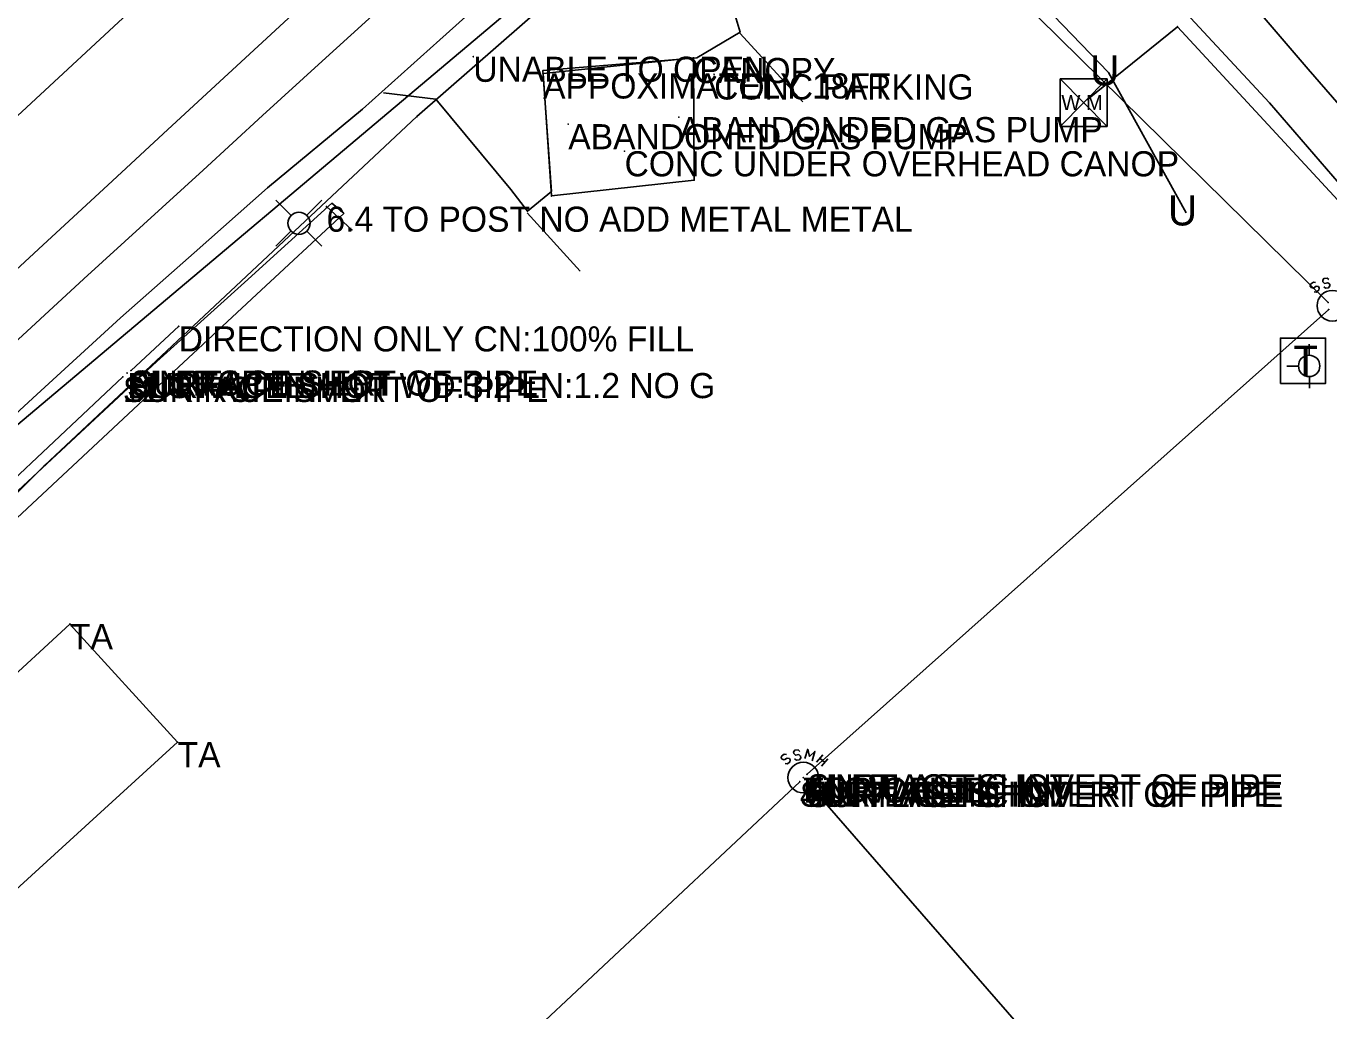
# Model space of a CAD drawing. Extents: x 1660112 to 1662239, y 668919 to 671377.
# Drawn here: x 1661444.9 to 1661704.2, y 669604.5 to 669800.5 of the extents above; entities that cross this region are included whole.
import ezdxf

# ---------------------------------------------------------------- set-up
doc = ezdxf.new("R2010")
doc.units = 0
for name, color, linetype in [('Default', 7, 'Continuous'), ('S_BASELINE', 7, 'Continuous'), ('S_BUILDING', 7, 'Continuous'), ('S_BUILDING_ANNOT', 7, 'Continuous'), ('S_DRG_PT_SYM', 7, 'Continuous'), ('S_DROP_INLET_ANNOT', 7, 'Continuous'), ('S_EDGE_CONCRETE', 7, 'Continuous'), ('S_EDGE_PAVEMENT', 7, 'Continuous'), ('S_FIBER_OPTIC_CABLE', 7, 'Continuous'), ('S_GRD_PT_SYM', 7, 'Continuous'), ('S_MANHOLE_ANNOT', 7, 'Continuous'), ('S_MISC_STRUCTURES', 7, 'Continuous'), ('S_MISC_STRUCTURES_ANNOT', 7, 'Continuous'), ('S_MISC_TOPO_POINT', 7, 'Continuous'), ('S_MSC_PT_SYM', 7, 'Continuous'), ('S_PAVEMENT_CROWN', 7, 'Continuous'), ('S_SANITARY_SEWER', 7, 'Continuous'), ('S_SANITARY_SEWER_ANNOT', 7, 'Continuous'), ('S_SIDEWALK', 7, 'Continuous'), ('S_SIGN', 7, 'Continuous'), ('S_SIGN_ANNOT', 7, 'Continuous'), ('S_STORM_SEWER', 7, 'Continuous'), ('S_STORM_SEWER_ANNOT', 7, 'Continuous'), ('S_STR_PT_SYM', 7, 'Continuous'), ('S_SURVEY_TEXT_ANNOT', 7, 'Continuous'), ('S_TELEPHONE_UTILITIES', 7, 'Continuous'), ('S_UNDERGROUND_CABLE', 7, 'Continuous'), ('S_UTILITY_POLE', 7, 'Continuous'), ('S_UTL_PT_SYM', 7, 'Continuous'), ('S_WATER_UTILITIES', 7, 'Continuous')]:
    doc.layers.add(name, color=color, linetype=linetype)

msp = doc.modelspace()

# ---------------------------------------------------------------- linework, layer by layer
at = {"layer": 'S_BASELINE'}
msp.add_line((1661604.59, 669857.12), (1660827.54, 669202.71), dxfattribs=at)
at = {"layer": 'S_BUILDING'}
for p, q in [((1661405.5, 669637.28), (1661453.66, 669681.54)), ((1661453.66, 669681.54), (1661475.08, 669658.04)), ((1661475.08, 669658.04), (1661427.04, 669614.25))]:
    msp.add_line(p, q, dxfattribs=at)
at = {"layer": 'S_DRG_PT_SYM'}
for points in [[(1661533.92, 669794.44), (1661533.92, 669794.49), (1661533.92, 669794.44), (1661533.87, 669794.44), (1661533.92, 669794.44), (1661533.92, 669794.39), (1661533.92, 669794.44), (1661533.97, 669794.44)], [(1661465.03, 669731.49), (1661465.03, 669731.54), (1661465.03, 669731.49), (1661464.98, 669731.49), (1661465.03, 669731.49), (1661465.03, 669731.44), (1661465.03, 669731.49), (1661465.08, 669731.49)]]:
    msp.add_lwpolyline(points, dxfattribs=at)
at = {"layer": 'S_EDGE_CONCRETE'}
for points in [[(1661586.93, 669799.09), (1661599.46, 669785.48)], [(1661544.63, 669763.36), (1661555.15, 669751.79)]]:
    msp.add_lwpolyline(points, dxfattribs=at)
at = {"layer": 'S_EDGE_PAVEMENT'}
for points in [[(1661432.01, 669741.93), (1661449.2, 669757.82), (1661461.17, 669768.88), (1661473.15, 669779.94), (1661485.12, 669791), (1661497.09, 669802.06), (1661512.08, 669815.85), (1661527.07, 669829.65), (1661544.05, 669845.51), (1661561.04, 669861.38), (1661565.83, 669865.41), (1661573.24, 669872.37), (1661579.19, 669880.3), (1661583.76, 669891.47), (1661584.04, 669901.2), (1661578.64, 669914.49), (1661567.83, 669926.75), (1661553.64, 669942.48), (1661544.41, 669952.61), (1661535.19, 669962.75), (1661525.02, 669973.56)], [(1661587.69, 669853.6), (1661601.46, 669861.14), (1661607.16, 669865.14), (1661611.7, 669864.55), (1661620.99, 669860.83), (1661627.24, 669857.2), (1661632.97, 669852.86), (1661640.64, 669844.85), (1661642.88, 669839.37), (1661651.88, 669829.25), (1661660.88, 669819.13), (1661676.63, 669802.18), (1661692.38, 669785.23), (1661706.18, 669769.2), (1661719.98, 669753.17), (1661729.11, 669743.19), (1661738.25, 669733.2), (1661747.38, 669723.22), (1661756.51, 669713.23), (1661766.96, 669701.85), (1661777.42, 669690.46), (1661787.87, 669679.07), (1661798.32, 669667.68)], [(1661516.06, 669787.26), (1661526.46, 669785.99), (1661541.4, 669768), (1661544.7, 669763.68), (1661549.49, 669767.62), (1661547.73, 669791.69), (1661563.07, 669792.95), (1661578.42, 669794.22), (1661586.99, 669799.3), (1661585.63, 669803.97), (1661600.8, 669818.33), (1661615.97, 669832.69), (1661602.41, 669845.81), (1661600.05, 669858.83)], [(1661428.9, 669710.52), (1661446.3, 669726.5), (1661463.7, 669742.47), (1661478.34, 669755.42), (1661492.99, 669768.37), (1661511.9, 669783.99), (1661527.23, 669797.8), (1661542.56, 669811.61)]]:
    msp.add_lwpolyline(points, dxfattribs=at)
at = {"layer": 'S_FIBER_OPTIC_CABLE'}
msp.add_line((1661442.32, 669781.84), (1661490.21, 669826.26), dxfattribs=at)
at = {"layer": 'S_GRD_PT_SYM'}
for points in [[(1661704.02, 669745.54), (1661704.02, 669745.59), (1661704.02, 669745.54), (1661703.97, 669745.54), (1661704.02, 669745.54), (1661704.02, 669745.49), (1661704.02, 669745.54), (1661704.07, 669745.54)], [(1661704.13, 669744.15), (1661704.13, 669744.2), (1661704.13, 669744.15), (1661704.08, 669744.15), (1661704.13, 669744.15), (1661704.13, 669744.1), (1661704.13, 669744.15), (1661704.18, 669744.15)], [(1661464.19, 669730.74), (1661464.19, 669730.79), (1661464.19, 669730.74), (1661464.14, 669730.74), (1661464.19, 669730.74), (1661464.19, 669730.69), (1661464.19, 669730.74), (1661464.24, 669730.74)], [(1661465.81, 669731.99), (1661465.81, 669732.04), (1661465.81, 669731.99), (1661465.76, 669731.99), (1661465.81, 669731.99), (1661465.81, 669731.94), (1661465.81, 669731.99), (1661465.86, 669731.99)], [(1661600.32, 669651.65), (1661600.32, 669651.7), (1661600.32, 669651.65), (1661600.27, 669651.65), (1661600.32, 669651.65), (1661600.32, 669651.6), (1661600.32, 669651.65), (1661600.37, 669651.65)], [(1661598.89, 669650.17), (1661598.89, 669650.22), (1661598.89, 669650.17), (1661598.84, 669650.17), (1661598.89, 669650.17), (1661598.89, 669650.12), (1661598.89, 669650.17), (1661598.94, 669650.17)], [(1661600.3, 669650.13), (1661600.3, 669650.18), (1661600.3, 669650.13), (1661600.25, 669650.13), (1661600.3, 669650.13), (1661600.3, 669650.08), (1661600.3, 669650.13), (1661600.35, 669650.13)]]:
    msp.add_lwpolyline(points, dxfattribs=at)
at = {"layer": 'S_MISC_STRUCTURES'}
for p, q in [((1661577.73, 669794.19), (1661547.8, 669791.12)), ((1661577.88, 669769.87), (1661577.73, 669794.19)), ((1661547.8, 669791.12), (1661549.46, 669766.72)), ((1661549.46, 669766.72), (1661577.88, 669769.87))]:
    msp.add_line(p, q, dxfattribs=at)
at = {"layer": 'S_MSC_PT_SYM'}
for points in [[(1661577.73, 669794.19), (1661577.73, 669794.24), (1661577.73, 669794.19), (1661577.68, 669794.19), (1661577.73, 669794.19), (1661577.73, 669794.14), (1661577.73, 669794.19), (1661577.78, 669794.19)], [(1661547.8, 669791.12), (1661547.8, 669791.17), (1661547.8, 669791.12), (1661547.75, 669791.12), (1661547.8, 669791.12), (1661547.8, 669791.07), (1661547.8, 669791.12), (1661547.85, 669791.12)], [(1661581.84, 669790.92), (1661581.84, 669790.97), (1661581.84, 669790.92), (1661581.79, 669790.92), (1661581.84, 669790.92), (1661581.84, 669790.87), (1661581.84, 669790.92), (1661581.89, 669790.92)], [(1661552.82, 669781.02), (1661552.82, 669781.07), (1661552.82, 669781.02), (1661552.77, 669781.02), (1661552.82, 669781.02), (1661552.82, 669780.97), (1661552.82, 669781.02), (1661552.87, 669781.02)], [(1661574.83, 669782.42), (1661574.83, 669782.47), (1661574.83, 669782.42), (1661574.78, 669782.42), (1661574.83, 669782.42), (1661574.83, 669782.36), (1661574.83, 669782.42), (1661574.88, 669782.42)], [(1661564.02, 669775.63), (1661564.02, 669775.68), (1661564.02, 669775.63), (1661563.97, 669775.63), (1661564.02, 669775.63), (1661564.02, 669775.58), (1661564.02, 669775.63), (1661564.07, 669775.63)], [(1661577.88, 669769.87), (1661577.88, 669769.92), (1661577.88, 669769.87), (1661577.83, 669769.87), (1661577.88, 669769.87), (1661577.88, 669769.82), (1661577.88, 669769.87), (1661577.93, 669769.87)], [(1661504.7, 669764.61), (1661504.7, 669764.66), (1661504.7, 669764.61), (1661504.65, 669764.61), (1661504.7, 669764.61), (1661504.7, 669764.56), (1661504.7, 669764.61), (1661504.75, 669764.61)], [(1661549.46, 669766.72), (1661549.46, 669766.77), (1661549.46, 669766.72), (1661549.41, 669766.72), (1661549.46, 669766.72), (1661549.46, 669766.67), (1661549.46, 669766.72), (1661549.51, 669766.72)], [(1661509.75, 669759.98), (1661509.75, 669760.03), (1661509.75, 669759.98), (1661509.7, 669759.98), (1661509.75, 669759.98), (1661509.75, 669759.93), (1661509.75, 669759.98), (1661509.8, 669759.98)]]:
    msp.add_lwpolyline(points, dxfattribs=at)
at = {"layer": 'S_PAVEMENT_CROWN'}
for points in [[(1661620.71, 669884.35), (1661629.13, 669874.34), (1661637.54, 669864.33), (1661653.63, 669845.85), (1661669.73, 669827.36), (1661684.9, 669809.66), (1661700.07, 669791.96), (1661714.09, 669775.77), (1661728.11, 669759.57), (1661736.98, 669749.7), (1661745.86, 669739.83), (1661754.73, 669729.96), (1661763.61, 669720.09), (1661774.08, 669708.76), (1661784.55, 669697.43), (1661795.03, 669686.1), (1661805.5, 669674.77)], [(1661438.95, 669734.2), (1661456.42, 669750.24), (1661468.28, 669761.06), (1661480.14, 669771.89), (1661492, 669782.71), (1661503.87, 669793.54), (1661518.86, 669807.19)]]:
    msp.add_lwpolyline(points, dxfattribs=at)
at = {"layer": 'S_SANITARY_SEWER'}
for p, q in [((1661704.02, 669745.54), (1661292.91, 670150.69)), ((1661700.53, 669749.19), (1661700.46, 669748.8)), ((1661700.46, 669748.8), (1661700.65, 669748.53)), ((1661701.08, 669749.58), (1661700.53, 669749.19)), ((1661701.5, 669749.5), (1661701.08, 669749.58)), ((1661700.65, 669748.53), (1661701.08, 669748.41)), ((1661701.08, 669748.41), (1661701.62, 669748.76)), ((1661701.62, 669747.6), (1661701.23, 669747.68)), ((1661701.62, 669748.76), (1661702.08, 669748.69)), ((1661702.16, 669747.99), (1661701.62, 669747.6)), ((1661702.08, 669748.69), (1661702.24, 669748.41)), ((1661702.24, 669748.41), (1661702.16, 669747.99)), ((1661704.13, 669744.15), (1661600.32, 669651.65)), ((1661595.8, 669655.67), (1661595.26, 669655.28)), ((1661596.23, 669655.59), (1661595.8, 669655.67)), ((1661602.23, 669654.04), (1661603.47, 669655.52)), ((1661595.26, 669655.28), (1661595.18, 669654.9)), ((1661595.18, 669654.9), (1661595.37, 669654.63)), ((1661595.37, 669654.63), (1661595.8, 669654.51)), ((1661595.8, 669654.51), (1661596.34, 669654.86)), ((1661596.34, 669653.7), (1661595.95, 669653.77)), ((1661596.34, 669654.86), (1661596.81, 669654.78)), ((1661596.88, 669654.08), (1661596.34, 669653.7)), ((1661596.81, 669654.78), (1661596.96, 669654.51)), ((1661596.96, 669654.51), (1661596.88, 669654.08)), ((1661602.89, 669654.82), (1661603.86, 669654.01)), ((1661604.44, 669654.7), (1661603.2, 669653.23)), ((1661598.89, 669650.17), (1661435.12, 669496.77)), ((1661600.3, 669650.13), (1661643.77, 669600.19))]:
    msp.add_line(p, q, dxfattribs=at)
for points in [[(1661704.18, 669750.12), (1661703.83, 669750.39), (1661703.17, 669750.31), (1661702.94, 669749.96), (1661702.98, 669749.65), (1661703.32, 669749.34), (1661703.94, 669749.46), (1661704.33, 669749.15), (1661704.37, 669748.84), (1661704.1, 669748.45), (1661703.48, 669748.38), (1661703.13, 669748.65)], [(1661598.9, 669656.21), (1661598.55, 669656.49), (1661597.89, 669656.41), (1661597.66, 669656.06), (1661597.7, 669655.75), (1661598.05, 669655.44), (1661598.67, 669655.56), (1661599.05, 669655.25), (1661599.09, 669654.94), (1661598.82, 669654.55), (1661598.2, 669654.47), (1661597.85, 669654.74)], [(1661601.34, 669654.35), (1661601.88, 669656.21), (1661600.84, 669655.21), (1661600.45, 669656.64), (1661599.91, 669654.78)]]:
    msp.add_lwpolyline(points, dxfattribs=at)
for centre in [(1661704.86, 669744.89), (1661599.58, 669650.98)]:
    msp.add_circle(centre, 3.05, dxfattribs=at)
at = {"layer": 'S_SIDEWALK'}
for points in [[(1661399.81, 669667.42), (1661409.03, 669676.05), (1661418.25, 669684.68), (1661427.46, 669693.31), (1661436.68, 669701.94), (1661453.82, 669717.86), (1661470.97, 669733.78), (1661488.36, 669749.53), (1661505.75, 669765.29), (1661508.14, 669763.29)], [(1661402.62, 669664.93), (1661420.84, 669681.92), (1661439.05, 669698.91), (1661456.19, 669714.89), (1661473.33, 669730.87), (1661490.76, 669747.1), (1661508.19, 669763.33)]]:
    msp.add_lwpolyline(points, dxfattribs=at)
at = {"layer": 'S_SIGN'}
msp.add_line((1661504.7, 669764.61), (1661509.75, 669759.98), dxfattribs=at)
at = {"layer": 'S_STORM_SEWER'}
for p, q in [((1661465.81, 669731.99), (1661475.29, 669740.79)), ((1661464.19, 669730.74), (1661337.5, 669611.48))]:
    msp.add_line(p, q, dxfattribs=at)
at = {"layer": 'S_STR_PT_SYM'}
for points in [[(1661453.66, 669681.54), (1661453.66, 669681.59), (1661453.66, 669681.54), (1661453.61, 669681.54), (1661453.66, 669681.54), (1661453.66, 669681.49), (1661453.66, 669681.54), (1661453.71, 669681.54)], [(1661475.08, 669658.04), (1661475.08, 669658.09), (1661475.08, 669658.04), (1661475.03, 669658.04), (1661475.08, 669658.04), (1661475.08, 669657.99), (1661475.08, 669658.04), (1661475.13, 669658.04)]]:
    msp.add_lwpolyline(points, dxfattribs=at)
at = {"layer": 'S_TELEPHONE_UTILITIES'}
msp.add_lwpolyline([(1661694.52, 669729.44), (1661694.52, 669738.44), (1661703.52, 669738.44), (1661703.52, 669729.44)], close=True, dxfattribs=at)
at = {"layer": 'S_UNDERGROUND_CABLE'}
for p, q in [((1661660.31, 669791.28), (1661639.6, 669812.78)), ((1661675.77, 669763.4), (1661660.31, 669791.28))]:
    msp.add_line(p, q, dxfattribs=at)
at = {"layer": 'S_UTILITY_POLE'}
for p, q in [((1661497.62, 669762.88), (1661494.64, 669765.86)), ((1661500.8, 669762.88), (1661503.79, 669765.86)), ((1661497.62, 669759.7), (1661494.64, 669756.72)), ((1661500.8, 669759.7), (1661503.79, 669756.72)), ((1661700.23, 669735.02), (1661700.23, 669737.26)), ((1661698.14, 669732.89), (1661695.82, 669732.89)), ((1661700.31, 669728.47), (1661700.31, 669730.79))]:
    msp.add_line(p, q, dxfattribs=at)
for centre, radius in [((1661499.22, 669761.3), 2.21), ((1661700.24, 669732.91), 2.13)]:
    msp.add_circle(centre, radius, dxfattribs=at)
at = {"layer": 'S_UTL_PT_SYM'}
for points in [[(1661674.04, 669800.4), (1661674.04, 669800.45), (1661674.04, 669800.4), (1661673.99, 669800.4), (1661674.04, 669800.4), (1661674.04, 669800.35), (1661674.04, 669800.4), (1661674.09, 669800.4)], [(1661656.12, 669785.92), (1661656.12, 669785.97), (1661656.12, 669785.92), (1661656.07, 669785.92), (1661656.12, 669785.92), (1661656.12, 669785.87), (1661656.12, 669785.92), (1661656.17, 669785.92)], [(1661522.71, 669782.51), (1661522.71, 669782.56), (1661522.71, 669782.51), (1661522.66, 669782.51), (1661522.71, 669782.51), (1661522.71, 669782.45), (1661522.71, 669782.51), (1661522.76, 669782.51)], [(1661704.02, 669745.54), (1661704.02, 669745.59), (1661704.02, 669745.54), (1661703.97, 669745.54), (1661704.02, 669745.54), (1661704.02, 669745.49), (1661704.02, 669745.54), (1661704.07, 669745.54)], [(1661704.13, 669744.15), (1661704.13, 669744.2), (1661704.13, 669744.15), (1661704.08, 669744.15), (1661704.13, 669744.15), (1661704.13, 669744.1), (1661704.13, 669744.15), (1661704.18, 669744.15)], [(1661475.29, 669740.79), (1661475.29, 669740.84), (1661475.29, 669740.79), (1661475.24, 669740.79), (1661475.29, 669740.79), (1661475.29, 669740.74), (1661475.29, 669740.79), (1661475.34, 669740.79)], [(1661464.19, 669730.74), (1661464.19, 669730.79), (1661464.19, 669730.74), (1661464.14, 669730.74), (1661464.19, 669730.74), (1661464.19, 669730.69), (1661464.19, 669730.74), (1661464.24, 669730.74)], [(1661465.03, 669731.49), (1661465.03, 669731.54), (1661465.03, 669731.49), (1661464.98, 669731.49), (1661465.03, 669731.49), (1661465.03, 669731.44), (1661465.03, 669731.49), (1661465.08, 669731.49)], [(1661465.81, 669731.99), (1661465.81, 669732.04), (1661465.81, 669731.99), (1661465.76, 669731.99), (1661465.81, 669731.99), (1661465.81, 669731.94), (1661465.81, 669731.99), (1661465.86, 669731.99)], [(1661448.56, 669713.08), (1661448.56, 669713.13), (1661448.56, 669713.08), (1661448.51, 669713.08), (1661448.56, 669713.08), (1661448.56, 669713.03), (1661448.56, 669713.08), (1661448.61, 669713.08)], [(1661599.58, 669650.98), (1661599.58, 669651.03), (1661599.58, 669650.98), (1661599.53, 669650.98), (1661599.58, 669650.98), (1661599.58, 669650.93), (1661599.58, 669650.98), (1661599.63, 669650.98)], [(1661600.32, 669651.65), (1661600.32, 669651.7), (1661600.32, 669651.65), (1661600.27, 669651.65), (1661600.32, 669651.65), (1661600.32, 669651.6), (1661600.32, 669651.65), (1661600.37, 669651.65)], [(1661598.89, 669650.17), (1661598.89, 669650.22), (1661598.89, 669650.17), (1661598.84, 669650.17), (1661598.89, 669650.17), (1661598.89, 669650.12), (1661598.89, 669650.17), (1661598.94, 669650.17)], [(1661600.3, 669650.13), (1661600.3, 669650.18), (1661600.3, 669650.13), (1661600.25, 669650.13), (1661600.3, 669650.13), (1661600.3, 669650.08), (1661600.3, 669650.13), (1661600.35, 669650.13)]]:
    msp.add_lwpolyline(points, dxfattribs=at)
at = {"layer": 'S_WATER_UTILITIES'}
for p, q in [((1661610.79, 669859.67), (1661522.71, 669782.51)), ((1661674.04, 669800.4), (1661656.12, 669785.92)), ((1661737.48, 669731.75), (1661674.04, 669800.4)), ((1661650.72, 669790.05), (1661660.06, 669790.05)), ((1661650.72, 669790.05), (1661650.72, 669780.56)), ((1661650.72, 669790.05), (1661660.06, 669780.56)), ((1661660.06, 669790.05), (1661650.72, 669780.56)), ((1661660.06, 669790.05), (1661660.06, 669780.56)), ((1661522.71, 669782.51), (1661448.56, 669713.08)), ((1661650.72, 669780.56), (1661660.06, 669780.56)), ((1661448.56, 669713.08), (1661375.21, 669639.9))]:
    msp.add_line(p, q, dxfattribs=at)

# ---------------------------------------------------------------- texts
at = {"layer": 'Default'}
for p in [(1661656.68, 669788.73), (1661672.15, 669760.86)]:
    msp.add_text('U', height=6, rotation=360, dxfattribs=at).set_placement(p)
at = {"layer": 'S_BUILDING_ANNOT'}
for p in [(1661453.66, 669676.54), (1661475.08, 669653.04)]:
    msp.add_text('TA', height=5, dxfattribs=at).set_placement(p)
at = {"layer": 'S_DROP_INLET_ANNOT'}
for s, p in [('UNABLE TO OPEN', (1661533.92, 669789.44)), ('SURFACE SHOT WD:3.2 LN:1.2 NO G', (1661465.03, 669726.49))]:
    msp.add_text(s, height=5, dxfattribs=at).set_placement(p)
at = {"layer": 'S_MANHOLE_ANNOT'}
for p in [(1661465.03, 669726.49), (1661599.58, 669645.98)]:
    msp.add_text('FLOW LINE', height=5, dxfattribs=at).set_placement(p)
at = {"layer": 'S_MISC_STRUCTURES_ANNOT'}
for s, p in [('CANOPY', (1661577.73, 669789.19)), ('APPOXIMATELY 18FT', (1661547.8, 669786.12))]:
    msp.add_text(s, height=5, dxfattribs=at).set_placement(p)
at = {"layer": 'S_MISC_TOPO_POINT'}
for p in [(1661464.19, 669725.74), (1661465.81, 669726.99), (1661600.32, 669646.65), (1661598.89, 669645.17), (1661600.3, 669645.13)]:
    msp.add_text('SURFACE SHOT', height=5, dxfattribs=at).set_placement(p)
at = {"layer": 'S_SANITARY_SEWER_ANNOT'}
for s, p in [('TOP OF LID', (1661599.58, 669645.98)), ('4IN PLASTIC INVERT OF PIPE', (1661600.32, 669646.65)), ('4IN PLASTIC INVERT OF PIPE', (1661598.89, 669645.17)), ('4IN PLASTIC INVERT OF PIPE', (1661600.3, 669645.13))]:
    msp.add_text(s, height=5, dxfattribs=at).set_placement(p)
at = {"layer": 'S_SIGN_ANNOT'}
msp.add_text('6.4 TO POST NO ADD METAL METAL', height=5, dxfattribs=at).set_placement((1661504.7, 669759.61))
at = {"layer": 'S_STORM_SEWER_ANNOT'}
for s, p in [('DIRECTION ONLY CN:100% FILL', (1661475.29, 669735.79)), ('12IN RCP INVERT OF PIPE', (1661464.19, 669725.74)), ('9IN RCP INVERT OF PIPE', (1661465.81, 669726.99))]:
    msp.add_text(s, height=5, dxfattribs=at).set_placement(p)
at = {"layer": 'S_SURVEY_TEXT_ANNOT'}
for s, p in [('CONC PARKING', (1661581.84, 669785.92)), ('ABANDONDED GAS PUMP', (1661574.83, 669777.42)), ('ABANDONED GAS PUMP', (1661552.82, 669776.02)), ('CONC UNDER OVERHEAD CANOP', (1661564.02, 669770.63))]:
    msp.add_text(s, height=5, dxfattribs=at).set_placement(p)
at = {"layer": 'S_TELEPHONE_UTILITIES'}
msp.add_text('T', height=6, rotation=360, dxfattribs=at).set_placement((1661697.09, 669730.94))
at = {"layer": 'S_WATER_UTILITIES'}
msp.add_text('W M', height=3, rotation=360, dxfattribs=at).set_placement((1661650.93, 669783.82))

doc.saveas('drawing.dxf')
